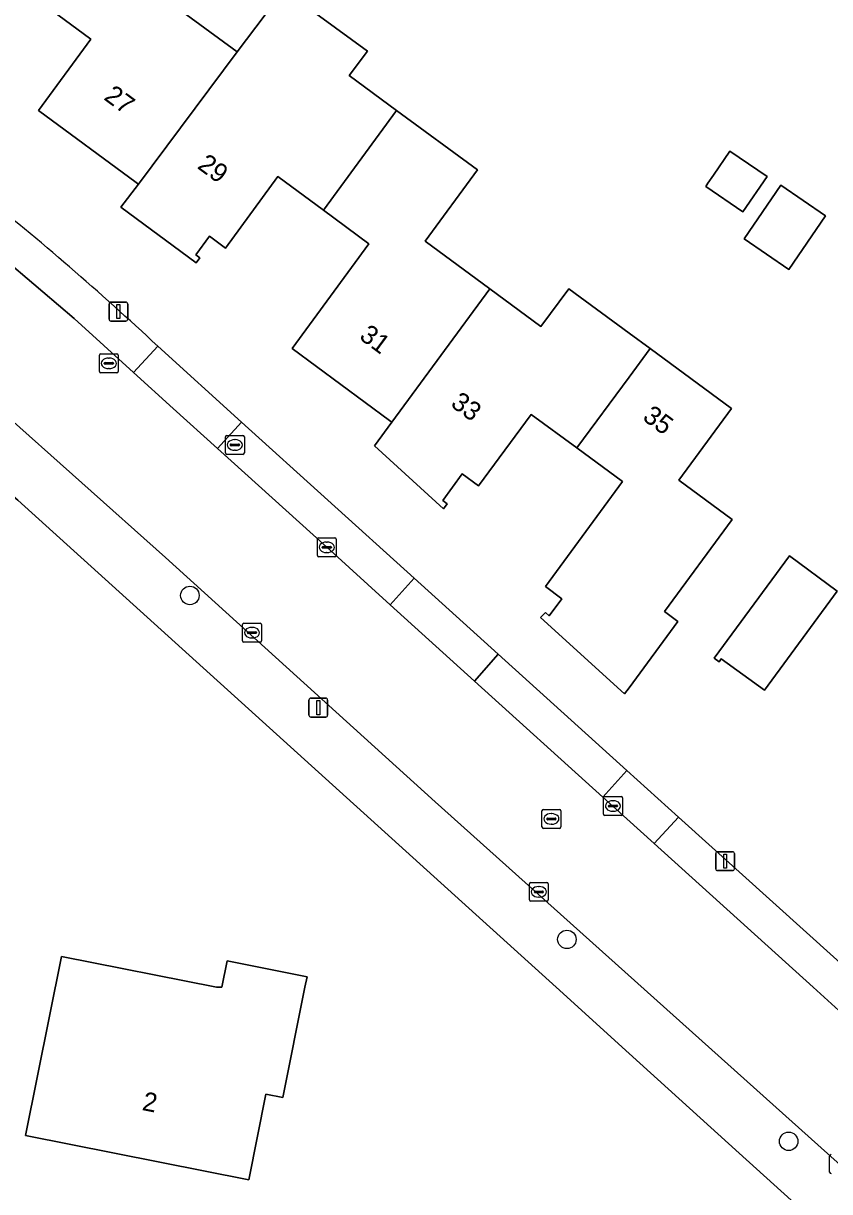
# Model space of a CAD drawing. Extents: x 163266 to 164362, y 381528 to 382286.
# Drawn here: x 163967.9 to 164010.6, y 381989.2 to 382051.1 of the extents above; entities that cross this region are included whole.
import ezdxf

# ---------------------------------------------------------------- set-up
doc = ezdxf.new("R2010")
doc.units = 0
for name, color, linetype in [('IMGEO_Boom', 7, 'Continuous'), ('IMGEO_Brandkraan', 7, 'Continuous'), ('IMGEO_Erf', 7, 'Continuous'), ('IMGEO_Kolk', 7, 'Continuous'), ('IMGEO_Lichtmast', 7, 'Continuous'), ('IMGEO_Pand', 7, 'Continuous'), ('IMGEO_Pand_nummerreeks', 7, 'Continuous'), ('IMGEO_Parkeervlak_open', 7, 'Continuous'), ('IMGEO_Rijbaan_lokaal_gesloten', 7, 'Continuous'), ('IMGEO_Rioolput', 7, 'Continuous'), ('IMGEO_Voetpad_open', 7, 'Continuous')]:
    doc.layers.add(name, color=color, linetype=linetype)

msp = doc.modelspace()

# ---------------------------------------------------------------- linework, layer by layer
at = {"layer": 'IMGEO_Boom'}
for centre in [(163976.738, 382020.756), (163996.708, 382002.537), (164008.457, 381991.844)]:
    msp.add_circle(centre, 0.489, dxfattribs=at)
at = {"layer": 'IMGEO_Brandkraan'}
for p, q in [((163978.696, 382029.23), (163979.548, 382029.23)), ((163978.621, 382028.304), (163978.621, 382029.156)), ((163978.88, 382028.724), (163978.88, 382028.736)), ((163979.318, 382028.687), (163978.92, 382028.687)), ((163978.923, 382028.773), (163979.321, 382028.773)), ((163979.109, 382029.01), (163979.134, 382029.01)), ((163979.364, 382028.736), (163979.364, 382028.724)), ((163979.622, 382029.156), (163979.622, 382028.304)), ((163979.548, 382028.23), (163978.696, 382028.23)), ((163979.132, 382028.45), (163979.107, 382028.45))]:
    msp.add_line(p, q, dxfattribs=at)
for points in [[(163978.696, 382029.23), (163979.548, 382029.23)], [(163978.621, 382028.304), (163978.621, 382029.156)], [(163979.622, 382029.156), (163979.622, 382028.304)], [(163979.548, 382028.23), (163978.696, 382028.23)]]:
    msp.add_lwpolyline(points, dxfattribs=at)
for centre, radius, start, end in [((163978.698, 382029.154), 0.0765, 91.55205, 178.44795), ((163978.698, 382029.154), 0.0765, 91.55205, 178.44795), ((163979.546, 382029.154), 0.0765, 1.55205, 88.44795), ((163979.546, 382029.154), 0.0765, 1.55205, 88.44795), ((163978.92, 382028.733), 0.0403, 85.87752, 175.75265), ((163978.917, 382028.723), 0.0366, 178.93798, 274.71019), ((163979.321, 382028.73), 0.043, 264.86636, 352.45326), ((163979.325, 382028.735), 0.0386, 1.73085, 96.63898), ((163978.698, 382028.306), 0.0765, 181.55205, 268.44795), ((163978.698, 382028.306), 0.0765, 181.55205, 268.44795), ((163979.546, 382028.306), 0.0765, 271.55205, 358.44795), ((163979.546, 382028.306), 0.0765, 271.55205, 358.44795)]:
    msp.add_arc(centre, radius, start, end, dxfattribs=at)
for centre, major_axis, ratio, start_param, end_param in [((163979.108, 382028.73), (-0.387, 0.002), 0.722429, 4.712389, 7.853982), ((163979.133, 382028.73), (-0.39, 0.002), 0.717154, 1.570796, 4.712389)]:
    msp.add_ellipse(centre, major_axis=major_axis, ratio=ratio, start_param=start_param, end_param=end_param, dxfattribs=at)
at = {"layer": 'IMGEO_Erf'}
for points in [[(163975.818, 382052.069), (163979.25, 382049.545), (163981.719, 382052.842), (163986.146, 382049.588), (163985.176, 382048.293), (163987.69, 382046.445), (163991.975, 382043.294), (163989.196, 382039.52), (163992.626, 382036.994), (163995.332, 382035.002), (163996.808, 382037.007), (164000, 382034.657), (164001.116, 382033.835), (164005.432, 382030.657), (164002.633, 382026.856), (164005.459, 382024.774), (164001.872, 382019.902), (164002.588, 382019.374), (164000, 382015.859), (163999.766, 382015.541), (163995.318, 382019.588), (163995.573, 382019.862), (163995.778, 382019.672), (163996.443, 382020.583), (163995.577, 382021.23), (163999.646, 382026.797), (163997.227, 382028.572), (163994.809, 382030.347), (163992.027, 382026.558), (163991.164, 382027.191), (163990.134, 382025.788), (163990.375, 382025.61), (163990.179, 382025.343), (163986.522, 382028.69), (163987.436, 382029.933), (163987.315, 382030.023), (163982.153, 382033.838), (163986.223, 382039.383), (163983.818, 382041.16), (163981.405, 382042.943), (163978.629, 382039.161), (163977.775, 382039.793), (163977.049, 382038.808), (163977.268, 382038.646), (163977.074, 382038.381), (163973.088, 382041.317), (163974.008, 382042.545), (163973.887, 382042.634), (163968.712, 382046.448), (163971.488, 382050.23), (163969.079, 382052.01)], [(163981.759, 381896.51), (163982.978, 381897.576), (163983.903, 381898.385), (164000, 381912.621), (164013.095, 381923.126), (164045.138, 381950.831), (164045.957, 381951.785), (164047.495, 381953.575), (164005.841, 381991.21), (164000, 381996.499), (163996.133, 382000), (163967.622, 382025.804), (163959.22, 382032.884), (163952.437, 382038.271), (163951.112, 382039.278), (163945.397, 382043.624), (163945.352, 382043.639), (163943.77, 382044.161)], [(163975.031, 382033.968), (163979.469, 382029.928), (163988.62, 382021.667), (163993.062, 382017.656), (163999.892, 382011.491), (164002.625, 382009.022), (164012.618, 382000), (164014.331, 381998.453), (164015.766, 381997.158), (164018.338, 381994.836)]]:
    msp.add_lwpolyline(points, dxfattribs=at)
for points in [[(164004.471, 382043.025), (164005.337, 382044.296), (164007.31, 382042.951), (164006.036, 382041.081), (164004.063, 382042.426), (164004.177, 382042.593)], [(164008.035, 382042.486), (164010.408, 382040.869), (164008.468, 382038.023), (164006.095, 382039.641)], [(164008.501, 382022.848), (164011.033, 382020.985), (164007.175, 382015.745), (164004.883, 382017.393), (164004.775, 382017.245), (164004.516, 382017.436)], [(163968.038, 381992.155), (163969.939, 382001.63), (163978.144, 382000), (163978.427, 382000), (163978.704, 382001.395), (163982.947, 382000.552), (163982.835, 382000), (163981.653, 381994.157), (163980.756, 381994.335), (163979.856, 381989.808)]]:
    msp.add_lwpolyline(points, close=True, dxfattribs=at)
msp.add_arc((163865.959, 381917.115), 159.848, 46.97244, 51.46813, dxfattribs=at)
at = {"layer": 'IMGEO_Kolk'}
for p, q in [((163983.489, 382022.881), (163983.489, 382023.733)), ((163983.564, 382023.807), (163984.416, 382023.807)), ((163984.49, 382023.733), (163984.49, 382022.881)), ((163983.748, 382023.301), (163983.748, 382023.313)), ((163984.186, 382023.264), (163983.788, 382023.264)), ((163983.791, 382023.35), (163984.189, 382023.35)), ((163984, 382023.027), (163983.975, 382023.027)), ((163983.977, 382023.587), (163984.002, 382023.587)), ((163984.232, 382023.313), (163984.232, 382023.301)), ((163984.416, 382022.807), (163983.564, 382022.807)), ((163979.527, 382018.359), (163979.527, 382019.211)), ((163979.602, 382019.285), (163980.454, 382019.285)), ((163979.786, 382018.779), (163979.786, 382018.791)), ((163980.224, 382018.742), (163979.826, 382018.742)), ((163979.829, 382018.828), (163980.227, 382018.828)), ((163980.015, 382019.065), (163980.04, 382019.065)), ((163980.27, 382018.791), (163980.27, 382018.779)), ((163980.528, 382019.211), (163980.528, 382018.359)), ((163980.454, 382018.285), (163979.602, 382018.285)), ((163980.038, 382018.505), (163980.013, 382018.505)), ((163998.65, 382009.18), (163998.65, 382010.032)), ((163998.725, 382010.106), (163999.577, 382010.106)), ((163999.651, 382010.032), (163999.651, 382009.18)), ((163998.909, 382009.6), (163998.909, 382009.612)), ((163999.347, 382009.563), (163998.949, 382009.563)), ((163998.952, 382009.649), (163999.35, 382009.649)), ((163999.138, 382009.886), (163999.163, 382009.886)), ((163999.393, 382009.612), (163999.393, 382009.6)), ((163999.577, 382009.106), (163998.725, 382009.106)), ((163999.161, 382009.326), (163999.136, 382009.326)), ((163994.722, 382004.63), (163994.722, 382005.482)), ((163994.797, 382005.556), (163995.649, 382005.556)), ((163994.981, 382005.05), (163994.981, 382005.062)), ((163995.024, 382005.099), (163995.422, 382005.099)), ((163995.21, 382005.336), (163995.235, 382005.336)), ((163995.465, 382005.062), (163995.465, 382005.05)), ((163995.723, 382005.482), (163995.723, 382004.63)), ((163995.649, 382004.556), (163994.797, 382004.556)), ((163995.419, 382005.013), (163995.021, 382005.013)), ((163995.233, 382004.776), (163995.208, 382004.776)), ((164010.627, 381990.213), (164010.627, 381991.065))]:
    msp.add_line(p, q, dxfattribs=at)
for points in [[(163983.489, 382022.881), (163983.489, 382023.733)], [(163983.564, 382023.807), (163984.416, 382023.807)], [(163984.49, 382023.733), (163984.49, 382022.881)], [(163984.416, 382022.807), (163983.564, 382022.807)], [(163979.527, 382018.359), (163979.527, 382019.211)], [(163979.602, 382019.285), (163980.454, 382019.285)], [(163980.528, 382019.211), (163980.528, 382018.359)], [(163980.454, 382018.285), (163979.602, 382018.285)], [(163998.65, 382009.18), (163998.65, 382010.032)], [(163998.725, 382010.106), (163999.577, 382010.106)], [(163999.651, 382010.032), (163999.651, 382009.18)], [(163999.577, 382009.106), (163998.725, 382009.106)], [(163994.722, 382004.63), (163994.722, 382005.482)], [(163994.797, 382005.556), (163995.649, 382005.556)], [(163995.723, 382005.482), (163995.723, 382004.63)], [(163995.649, 382004.556), (163994.797, 382004.556)], [(164010.627, 381990.213), (164010.627, 381991.065)]]:
    msp.add_lwpolyline(points, dxfattribs=at)
for centre, radius, start, end in [((163983.566, 382023.731), 0.0765, 91.55205, 178.44795), ((163983.566, 382023.731), 0.0765, 91.55205, 178.44795), ((163984.414, 382023.731), 0.0765, 1.55205, 88.44795), ((163984.414, 382023.731), 0.0765, 1.55205, 88.44795), ((163983.788, 382023.31), 0.0403, 85.87752, 175.75265), ((163983.785, 382023.3), 0.0366, 178.93798, 274.71019), ((163984.189, 382023.307), 0.043, 264.86636, 352.45326), ((163984.193, 382023.312), 0.0386, 1.73085, 96.63898), ((163983.566, 382022.883), 0.0765, 181.55205, 268.44795), ((163983.566, 382022.883), 0.0765, 181.55205, 268.44795), ((163984.414, 382022.883), 0.0765, 271.55205, 358.44795), ((163984.414, 382022.883), 0.0765, 271.55205, 358.44795), ((163979.604, 382019.209), 0.0765, 91.55205, 178.44795), ((163979.604, 382019.209), 0.0765, 91.55205, 178.44795), ((163979.826, 382018.788), 0.0403, 85.87752, 175.75265), ((163979.823, 382018.778), 0.0366, 178.93798, 274.71019), ((163980.227, 382018.785), 0.043, 264.86636, 352.45326), ((163980.231, 382018.79), 0.0386, 1.73085, 96.63898), ((163980.452, 382019.209), 0.0765, 1.55205, 88.44795), ((163980.452, 382019.209), 0.0765, 1.55205, 88.44795), ((163979.604, 382018.361), 0.0765, 181.55205, 268.44795), ((163979.604, 382018.361), 0.0765, 181.55205, 268.44795), ((163980.452, 382018.361), 0.0765, 271.55205, 358.44795), ((163980.452, 382018.361), 0.0765, 271.55205, 358.44795), ((163998.727, 382010.03), 0.0765, 91.55205, 178.44795), ((163998.727, 382010.03), 0.0765, 91.55205, 178.44795), ((163999.575, 382010.03), 0.0765, 1.55205, 88.44795), ((163999.575, 382010.03), 0.0765, 1.55205, 88.44795), ((163998.949, 382009.609), 0.0403, 85.87752, 175.75265), ((163998.946, 382009.599), 0.0366, 178.93798, 274.71019), ((163999.35, 382009.606), 0.043, 264.86636, 352.45326), ((163999.354, 382009.611), 0.0386, 1.73085, 96.63898), ((163998.727, 382009.182), 0.0765, 181.55205, 268.44795), ((163998.727, 382009.182), 0.0765, 181.55205, 268.44795), ((163999.575, 382009.182), 0.0765, 271.55205, 358.44795), ((163999.575, 382009.182), 0.0765, 271.55205, 358.44795), ((163994.799, 382005.48), 0.0765, 91.55205, 178.44795), ((163994.799, 382005.48), 0.0765, 91.55205, 178.44795), ((163995.021, 382005.059), 0.0403, 85.87752, 175.75265), ((163995.426, 382005.061), 0.0386, 1.73085, 96.63898), ((163995.647, 382005.48), 0.0765, 1.55205, 88.44795), ((163995.647, 382005.48), 0.0765, 1.55205, 88.44795), ((163994.799, 382004.632), 0.0765, 181.55205, 268.44795), ((163994.799, 382004.632), 0.0765, 181.55205, 268.44795), ((163995.018, 382005.049), 0.0366, 178.93798, 274.71019), ((163995.422, 382005.056), 0.043, 264.86636, 352.45326), ((163995.647, 382004.632), 0.0765, 271.55205, 358.44795), ((163995.647, 382004.632), 0.0765, 271.55205, 358.44795), ((164010.704, 381991.063), 0.0765, 91.55205, 178.44795), ((164010.704, 381991.063), 0.0765, 91.55205, 178.44795), ((164010.704, 381990.215), 0.0765, 181.55205, 268.44795), ((164010.704, 381990.215), 0.0765, 181.55205, 268.44795)]:
    msp.add_arc(centre, radius, start, end, dxfattribs=at)
for centre, major_axis, ratio, start_param, end_param in [((163983.976, 382023.307), (-0.387, 0.002), 0.722429, 4.712389, 7.853982), ((163984.001, 382023.307), (-0.39, 0.002), 0.717154, 1.570796, 4.712389), ((163980.014, 382018.785), (-0.387, 0.002), 0.722429, 4.712389, 7.853982), ((163980.039, 382018.785), (-0.39, 0.002), 0.717154, 1.570796, 4.712389), ((163999.137, 382009.606), (-0.387, 0.002), 0.722429, 4.712389, 7.853982), ((163999.162, 382009.606), (-0.39, 0.002), 0.717154, 1.570796, 4.712389), ((163995.209, 382005.056), (-0.387, 0.002), 0.722429, 4.712389, 7.853982), ((163995.234, 382005.056), (-0.39, 0.002), 0.717154, 1.570796, 4.712389)]:
    msp.add_ellipse(centre, major_axis=major_axis, ratio=ratio, start_param=start_param, end_param=end_param, dxfattribs=at)
at = {"layer": 'IMGEO_Lichtmast'}
for p, q in [((163972.453, 382035.394), (163972.453, 382036.194)), ((163972.453, 382036.194), (163972.453, 382035.394)), ((163972.553, 382036.294), (163973.343, 382036.294)), ((163973.343, 382036.294), (163972.553, 382036.294)), ((163973.443, 382036.194), (163973.443, 382035.394)), ((163973.443, 382035.394), (163973.443, 382036.194)), ((163973.343, 382035.294), (163972.553, 382035.294)), ((163972.553, 382035.294), (163973.343, 382035.294)), ((163983.044, 382014.417), (163983.044, 382015.217)), ((163983.044, 382015.217), (163983.044, 382014.417)), ((163983.144, 382015.317), (163983.934, 382015.317)), ((163983.934, 382015.317), (163983.144, 382015.317)), ((163984.034, 382015.217), (163984.034, 382014.417)), ((163984.034, 382014.417), (163984.034, 382015.217)), ((163983.934, 382014.317), (163983.144, 382014.317)), ((163983.144, 382014.317), (163983.934, 382014.317)), ((164004.595, 382006.283), (164004.595, 382007.083)), ((164004.595, 382007.083), (164004.595, 382006.283)), ((164004.695, 382007.183), (164005.485, 382007.183)), ((164005.485, 382007.183), (164004.695, 382007.183)), ((164005.585, 382007.083), (164005.585, 382006.283)), ((164005.585, 382006.283), (164005.585, 382007.083)), ((164005.485, 382006.183), (164004.695, 382006.183)), ((164004.695, 382006.183), (164005.485, 382006.183))]:
    msp.add_line(p, q, dxfattribs=at)
for points in [[(163972.873, 382036.169), (163973.023, 382036.169), (163973.023, 382035.419), (163972.873, 382035.419), (163972.873, 382036.169)], [(163983.464, 382015.192), (163983.614, 382015.192), (163983.614, 382014.442), (163983.464, 382014.442), (163983.464, 382015.192)], [(164005.015, 382007.058), (164005.165, 382007.058), (164005.165, 382006.308), (164005.015, 382006.308), (164005.015, 382007.058)]]:
    msp.add_lwpolyline(points, dxfattribs=at)
for centre, start, end in [((163972.553, 382036.194), 90, 180), ((163972.553, 382036.194), 90, 180), ((163973.343, 382036.194), 0, 90), ((163973.343, 382036.194), 360, 90), ((163972.553, 382035.394), 180, 270), ((163972.553, 382035.394), 180, 270), ((163973.343, 382035.394), 270, 0), ((163973.343, 382035.394), 270, 0), ((163983.144, 382015.217), 90, 180), ((163983.144, 382015.217), 90, 180), ((163983.934, 382015.217), 0, 90), ((163983.934, 382015.217), 360, 90), ((163983.144, 382014.417), 180, 270), ((163983.144, 382014.417), 180, 270), ((163983.934, 382014.417), 270, 0), ((163983.934, 382014.417), 270, 0), ((164004.695, 382007.083), 90, 180), ((164004.695, 382007.083), 90, 180), ((164005.485, 382007.083), 0, 90), ((164005.485, 382007.083), 360, 90), ((164004.695, 382006.283), 180, 270), ((164004.695, 382006.283), 180, 270), ((164005.485, 382006.283), 270, 0), ((164005.485, 382006.283), 270, 0)]:
    msp.add_arc(centre, 0.1, start, end, dxfattribs=at)
at = {"layer": 'IMGEO_Pand'}
for points in [[(163979.25, 382049.545), (163975.818, 382052.069), (163977.299, 382054.083), (163972.989, 382057.252), (163969.079, 382052.01), (163971.488, 382050.23), (163968.712, 382046.448), (163973.887, 382042.634), (163974.008, 382042.545)], [(163987.69, 382046.445), (163985.176, 382048.293), (163986.146, 382049.588), (163981.719, 382052.842), (163979.25, 382049.545), (163974.008, 382042.545), (163973.088, 382041.317), (163977.074, 382038.381), (163977.268, 382038.646), (163977.049, 382038.808), (163977.775, 382039.793), (163978.629, 382039.161), (163981.405, 382042.943), (163983.818, 382041.16)], [(163989.196, 382039.52), (163991.975, 382043.294), (163987.69, 382046.445), (163983.818, 382041.16), (163986.223, 382039.383), (163982.153, 382033.838), (163987.315, 382030.023), (163987.436, 382029.933), (163992.626, 382036.994)], [(164004.063, 382042.426), (164006.036, 382041.081), (164007.31, 382042.951), (164005.337, 382044.296), (164004.471, 382043.025), (164004.177, 382042.593)], [(164006.095, 382039.641), (164008.468, 382038.023), (164010.408, 382040.869), (164008.035, 382042.486)], [(164000, 382032.325), (164001.116, 382033.835), (164000, 382034.657), (163996.808, 382037.007), (163995.332, 382035.002), (163992.626, 382036.994), (163987.436, 382029.933), (163986.522, 382028.69), (163990.179, 382025.343), (163990.375, 382025.61), (163990.134, 382025.788), (163991.164, 382027.191), (163992.027, 382026.558), (163994.809, 382030.347), (163997.227, 382028.572)], [(163997.227, 382028.572), (163999.646, 382026.797), (163995.577, 382021.23), (163996.443, 382020.583), (163995.778, 382019.672), (163995.573, 382019.862), (163995.318, 382019.588), (163999.766, 382015.541), (164000, 382015.859), (164002.588, 382019.374), (164001.872, 382019.902), (164005.459, 382024.774), (164002.633, 382026.856), (164005.432, 382030.657), (164001.116, 382033.835), (164000, 382032.325)], [(164007.175, 382015.745), (164011.033, 382020.985), (164008.501, 382022.848), (164004.516, 382017.436), (164004.775, 382017.245), (164004.883, 382017.393)], [(163982.835, 382000), (163982.947, 382000.552), (163978.704, 382001.395), (163978.427, 382000), (163978.144, 382000), (163969.939, 382001.63), (163968.038, 381992.155), (163979.856, 381989.808), (163980.756, 381994.335), (163981.653, 381994.157)]]:
    msp.add_lwpolyline(points, close=True, dxfattribs=at)
at = {"layer": 'IMGEO_Parkeervlak_open'}
msp.add_lwpolyline([(163965.536, 382042.158), (163964.425, 382040.675), (163967.293, 382038.261), (163970.609, 382035.429), (163973.746, 382032.575), (163975.031, 382033.968)], dxfattribs=at)
for points in [[(163983.989, 382023.307), (163987.343, 382020.269), (163988.62, 382021.667), (163979.469, 382029.928), (163978.204, 382028.536)], [(163993.062, 382017.656), (163991.814, 382016.226), (163998.616, 382010.079), (163999.892, 382011.491)]]:
    msp.add_lwpolyline(points, close=True, dxfattribs=at)
msp.add_arc((163865.959, 381917.115), 159.848, 46.97244, 51.46813, dxfattribs=at)
at = {"layer": 'IMGEO_Rijbaan_lokaal_gesloten'}
msp.add_lwpolyline([(164013.055, 381997.013), (164009.749, 382000), (164001.325, 382007.61), (163998.616, 382010.079), (163991.814, 382016.226), (163987.343, 382020.269), (163983.989, 382023.307), (163978.204, 382028.536), (163975.853, 382030.668), (163973.746, 382032.575), (163970.609, 382035.429), (163967.293, 382038.261), (163964.425, 382040.675), (163959.63, 382044.367), (163956.865, 382046.445), (163953.343, 382049.082), (163951.353, 382050.557), (163947.738, 382045.71), (163957.994, 382037.828), (163966.57, 382030.683), (163975.454, 382022.768), (163989.724, 382009.823), (164011.535, 381990.277)], dxfattribs=at)
at = {"layer": 'IMGEO_Rioolput'}
for p, q in [((163972.02, 382033.552), (163972.872, 382033.552)), ((163971.945, 382032.626), (163971.945, 382033.478)), ((163972.204, 382033.046), (163972.204, 382033.058)), ((163972.642, 382033.009), (163972.244, 382033.009)), ((163972.247, 382033.095), (163972.645, 382033.095)), ((163972.433, 382033.332), (163972.458, 382033.332)), ((163972.688, 382033.058), (163972.688, 382033.046)), ((163972.946, 382033.478), (163972.946, 382032.626)), ((163972.872, 382032.552), (163972.02, 382032.552)), ((163972.456, 382032.772), (163972.431, 382032.772)), ((163995.463, 382009.421), (163996.315, 382009.421)), ((163995.388, 382008.495), (163995.388, 382009.347)), ((163995.647, 382008.915), (163995.647, 382008.927)), ((163996.085, 382008.878), (163995.687, 382008.878)), ((163995.69, 382008.964), (163996.088, 382008.964)), ((163995.876, 382009.201), (163995.901, 382009.201)), ((163996.131, 382008.927), (163996.131, 382008.915)), ((163996.389, 382009.347), (163996.389, 382008.495)), ((163996.315, 382008.421), (163995.463, 382008.421)), ((163995.899, 382008.641), (163995.874, 382008.641))]:
    msp.add_line(p, q, dxfattribs=at)
for points in [[(163972.02, 382033.552), (163972.872, 382033.552)], [(163971.945, 382032.626), (163971.945, 382033.478)], [(163972.946, 382033.478), (163972.946, 382032.626)], [(163972.872, 382032.552), (163972.02, 382032.552)], [(163995.463, 382009.421), (163996.315, 382009.421)], [(163995.388, 382008.495), (163995.388, 382009.347)], [(163996.389, 382009.347), (163996.389, 382008.495)], [(163996.315, 382008.421), (163995.463, 382008.421)]]:
    msp.add_lwpolyline(points, dxfattribs=at)
for centre, radius, start, end in [((163972.022, 382033.476), 0.0765, 91.55205, 178.44795), ((163972.022, 382033.476), 0.0765, 91.55205, 178.44795), ((163972.87, 382033.476), 0.0765, 1.55205, 88.44795), ((163972.87, 382033.476), 0.0765, 1.55205, 88.44795), ((163972.244, 382033.055), 0.0403, 85.87752, 175.75265), ((163972.241, 382033.045), 0.0366, 178.93798, 274.71019), ((163972.645, 382033.052), 0.043, 264.86636, 352.45326), ((163972.649, 382033.057), 0.0386, 1.73085, 96.63898), ((163972.022, 382032.628), 0.0765, 181.55205, 268.44795), ((163972.022, 382032.628), 0.0765, 181.55205, 268.44795), ((163972.87, 382032.628), 0.0765, 271.55205, 358.44795), ((163972.87, 382032.628), 0.0765, 271.55205, 358.44795), ((163995.465, 382009.345), 0.0765, 91.55205, 178.44795), ((163995.465, 382009.345), 0.0765, 91.55205, 178.44795), ((163996.313, 382009.345), 0.0765, 1.55205, 88.44795), ((163996.313, 382009.345), 0.0765, 1.55205, 88.44795), ((163995.687, 382008.924), 0.0403, 85.87752, 175.75265), ((163995.684, 382008.914), 0.0366, 178.93798, 274.71019), ((163996.088, 382008.921), 0.043, 264.86636, 352.45326), ((163996.092, 382008.926), 0.0386, 1.73085, 96.63898), ((163995.465, 382008.497), 0.0765, 181.55205, 268.44795), ((163995.465, 382008.497), 0.0765, 181.55205, 268.44795), ((163996.313, 382008.497), 0.0765, 271.55205, 358.44795), ((163996.313, 382008.497), 0.0765, 271.55205, 358.44795)]:
    msp.add_arc(centre, radius, start, end, dxfattribs=at)
for centre, major_axis, ratio, start_param, end_param in [((163972.432, 382033.052), (-0.387, 0.002), 0.722429, 4.712389, 7.853982), ((163972.457, 382033.052), (-0.39, 0.002), 0.717154, 1.570796, 4.712389), ((163995.875, 382008.921), (-0.387, 0.002), 0.722429, 4.712389, 7.853982), ((163995.9, 382008.921), (-0.39, 0.002), 0.717154, 1.570796, 4.712389)]:
    msp.add_ellipse(centre, major_axis=major_axis, ratio=ratio, start_param=start_param, end_param=end_param, dxfattribs=at)
at = {"layer": 'IMGEO_Voetpad_open'}
for points in [[(163942.334, 382045.958), (163942.351, 382045.94), (163945.348, 382043.661), (163945.352, 382043.639), (163945.397, 382043.624), (163951.112, 382039.278), (163952.437, 382038.271), (163959.22, 382032.884), (163967.622, 382025.804), (163996.133, 382000), (164000, 381996.499), (164005.841, 381991.21), (164047.495, 381953.575), (164050.865, 381950.343), (164050.939, 381950.414)], [(164027.042, 381976.258), (164026.418, 381976.805), (164011.535, 381990.277), (163989.724, 382009.823), (163975.454, 382022.768), (163966.57, 382030.683), (163957.994, 382037.828), (163947.738, 382045.71), (163947.652, 382045.773)]]:
    msp.add_lwpolyline(points, dxfattribs=at)
for points in [[(163975.853, 382030.668), (163978.204, 382028.536), (163979.469, 382029.928), (163975.031, 382033.968), (163973.746, 382032.575)], [(163991.814, 382016.226), (163993.062, 382017.656), (163988.62, 382021.667), (163987.343, 382020.269)], [(163999.892, 382011.491), (163998.616, 382010.079), (164001.325, 382007.61), (164002.625, 382009.022)], [(164002.625, 382009.022), (164001.325, 382007.61), (164009.749, 382000), (164013.055, 381997.013), (164014.331, 381998.453), (164012.618, 382000)]]:
    msp.add_lwpolyline(points, close=True, dxfattribs=at)

# ---------------------------------------------------------------- texts
at = {"layer": 'IMGEO_Pand_nummerreeks'}
for s, rotation, p in [('27', 323.61145, (163972.13, 382047.059)), ('29', 323.78334, (163977.081, 382043.418)), ('31', 323.53124, (163985.659, 382034.381)), ('33', 323.66875, (163990.498, 382030.811)), ('35', 323.63467, (164000.664, 382030.095)), ('2', 348.7643, (163974.167, 381993.507))]:
    msp.add_text(s, height=1, rotation=rotation, dxfattribs=at).set_placement(p)

doc.saveas('drawing.dxf')
